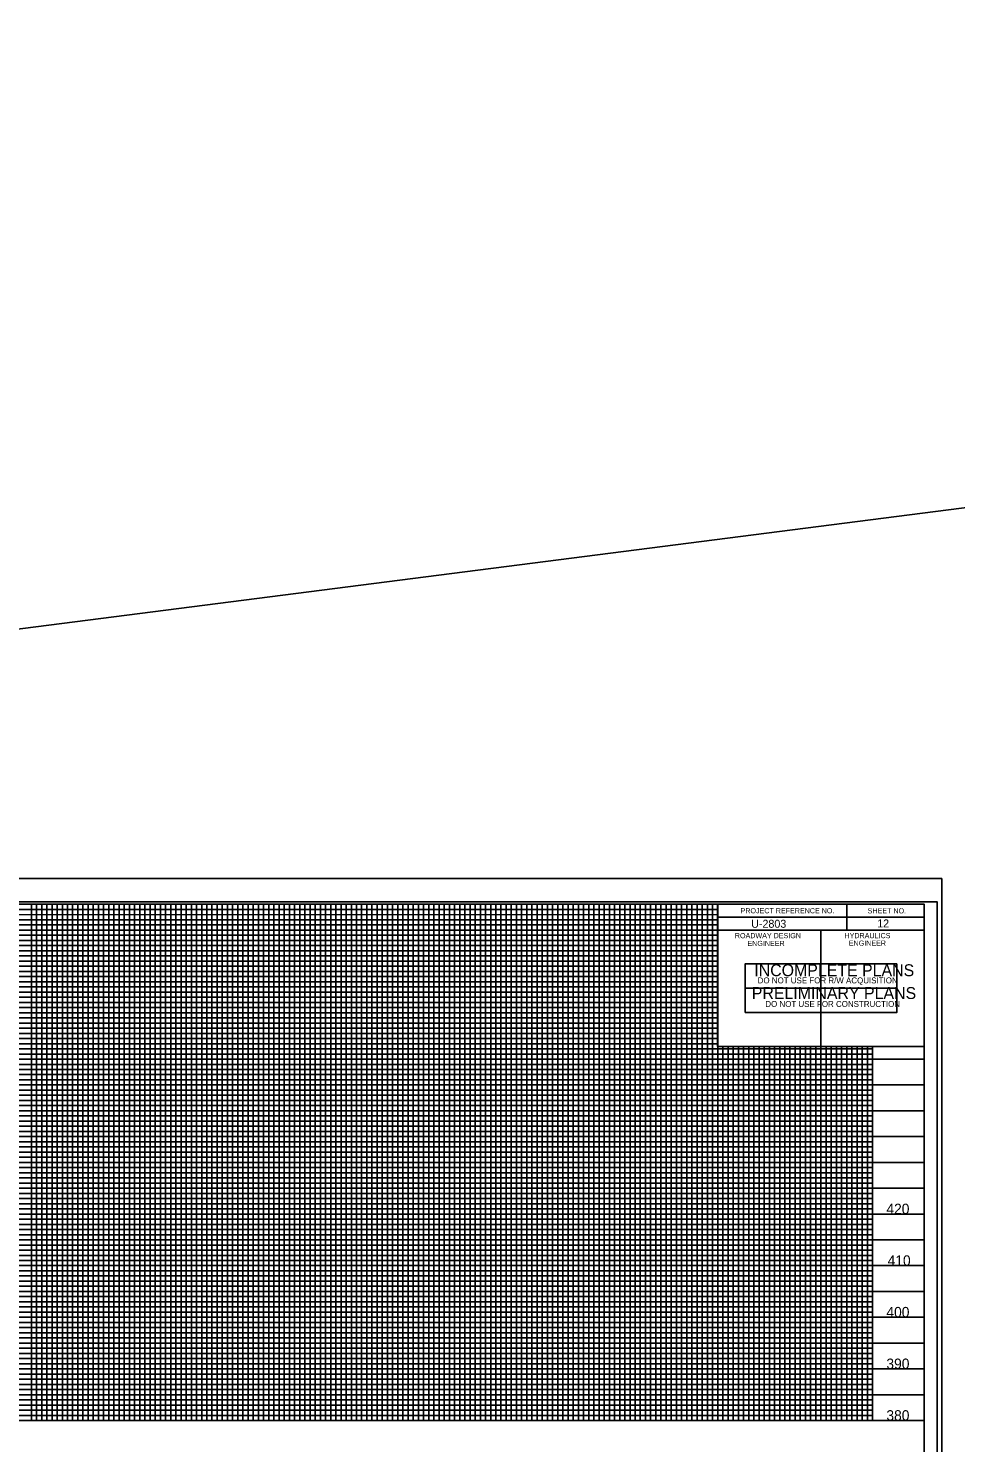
# Model space of a CAD drawing. Extents: x 571503 to 593215, y -77195 to -51828.
# Drawn here: x 588685 to 589583, y -53198 to -51828 of the extents above; entities that cross this region are included whole.
import ezdxf

# ---------------------------------------------------------------- set-up
doc = ezdxf.new("R2010")
doc.units = 0
for name, color, linetype in [('Exist Vertical Profile Vertical Axis Label', 7, 'Continuous'), ('Prop PFL Text', 7, 'Continuous'), ('Sheet Clip Boundary CELL', 7, 'Continuous'), ('Sheet Data Field CELL', 7, 'Continuous'), ('Sheet DOT Grid CELL', 7, 'Continuous'), ('Sheet Plot Border Inside CELL', 7, 'Continuous'), ('Sheet Plot Border Outside CELL', 7, 'Continuous'), ('Sheet Profile CELL', 7, 'Continuous'), ('Sheet Profile Grid Major CELL', 7, 'Continuous'), ('Sheet Profile Grid Middle CELL', 7, 'Continuous'), ('Sheet Profile Grid Minor CELL', 7, 'Continuous'), ('Sheet Sticker Incomplete CELL', 7, 'Continuous'), ('Sheet Sticker Preliminary CELL', 7, 'Continuous')]:
    doc.layers.add(name, color=color, linetype=linetype)

msp = doc.modelspace()

# ---------------------------------------------------------------- linework, layer by layer
at = {"layer": 'Prop PFL Text'}
msp.add_line((571799.6, -54572.4), (593215.4, -51828.4), dxfattribs=at)
at = {"layer": 'Sheet Clip Boundary CELL'}
msp.add_lwpolyline([(588102.5, -52676.9), (588102.5, -53176.9), (589502.5, -53176.9), (589502.5, -52814.5), (589352.4, -52814.5), (589352.4, -52676.9)], close=True, dxfattribs=at)
at = {"layer": 'Sheet DOT Grid CELL'}
for p, q in [((588702.5, -53176.9), (588702.5, -52676.9)), ((588702.5, -53176.9), (588702.5, -52676.9)), ((588752.5, -53176.9), (588752.5, -52676.9)), ((588752.5, -53176.9), (588752.5, -52676.9)), ((588802.5, -53176.9), (588802.5, -52676.9)), ((588802.5, -53176.9), (588802.5, -52676.9)), ((588852.5, -53176.9), (588852.5, -52676.9)), ((588852.5, -53176.9), (588852.5, -52676.9)), ((588902.5, -53176.9), (588902.5, -52676.9)), ((588902.5, -53176.9), (588902.5, -52676.9)), ((588952.5, -53176.9), (588952.5, -52676.9)), ((588952.5, -53176.9), (588952.5, -52676.9)), ((589002.5, -53176.9), (589002.5, -52676.9)), ((589002.5, -53176.9), (589002.5, -52676.9)), ((589052.5, -53176.9), (589052.5, -52676.9)), ((589052.5, -53176.9), (589052.5, -52676.9)), ((589102.5, -53176.9), (589102.5, -52676.9)), ((589102.5, -53176.9), (589102.5, -52676.9)), ((589152.5, -53176.9), (589152.5, -52676.9)), ((589152.5, -53176.9), (589152.5, -52676.9)), ((589202.5, -53176.9), (589202.5, -52676.9)), ((589202.5, -53176.9), (589202.5, -52676.9)), ((589252.5, -53176.9), (589252.5, -52676.9)), ((589252.5, -53176.9), (589252.5, -52676.9)), ((589302.5, -53176.9), (589302.5, -52676.9)), ((589302.5, -53176.9), (589302.5, -52676.9)), ((588052.5, -52726.9), (589352.4, -52726.9)), ((589352.4, -52726.9), (588052.5, -52726.9)), ((588052.5, -52776.9), (589352.4, -52776.9)), ((589352.4, -52776.9), (588052.5, -52776.9)), ((588052.5, -52826.9), (589552.5, -52826.9)), ((589552.5, -52826.9), (588052.5, -52826.9)), ((589352.5, -53176.9), (589352.5, -52814.5)), ((589352.5, -53176.9), (589352.5, -52814.5)), ((589402.5, -53176.9), (589402.5, -52814.5)), ((589402.5, -53176.9), (589402.5, -52814.5)), ((589452.5, -53176.9), (589452.5, -52814.5)), ((589452.5, -53176.9), (589452.5, -52814.5)), ((589502.5, -53176.9), (589502.5, -52814.5)), ((589502.5, -53176.9), (589502.5, -52814.5)), ((589552.5, -53176.9), (589552.5, -52814.5)), ((588052.5, -52876.9), (589552.5, -52876.9)), ((589552.5, -52876.9), (588052.5, -52876.9)), ((588052.5, -52926.9), (589552.5, -52926.9)), ((589552.5, -52926.9), (588052.5, -52926.9)), ((588052.5, -52976.9), (589552.5, -52976.9)), ((589552.5, -52976.9), (588052.5, -52976.9)), ((588052.5, -53026.9), (589552.5, -53026.9)), ((589552.5, -53026.9), (588052.5, -53026.9)), ((588052.5, -53076.9), (589552.5, -53076.9)), ((589552.5, -53076.9), (588052.5, -53076.9)), ((588052.5, -53126.9), (589552.5, -53126.9)), ((589552.5, -53126.9), (588052.5, -53126.9))]:
    msp.add_line(p, q, dxfattribs=at)
at = {"layer": 'Sheet Plot Border Inside CELL'}
msp.add_lwpolyline([(587898.5, -53729.5), (589565, -53729.5), (589565, -52674.4), (587898.5, -52674.4)], close=True, dxfattribs=at)
at = {"layer": 'Sheet Plot Border Outside CELL'}
msp.add_lwpolyline([(587885.5, -53751.9), (589569.5, -53751.9), (589569.5, -52651.9), (587885.5, -52651.9)], close=True, dxfattribs=at)
at = {"layer": 'Sheet Profile CELL'}
for p, q in [((589569.5, -52651.9), (587885.5, -52651.9)), ((589477.5, -52677), (589477.5, -52702)), ((589352.4, -52689.5), (589552.5, -52689.5)), ((589452.5, -52702), (589452.5, -52814.4)), ((588052.5, -53176.9), (589552.5, -53176.9))]:
    msp.add_line(p, q, dxfattribs=at)
for points in [[(589552.5, -52676.9), (588052.5, -52676.9), (588052.5, -53726.9), (589552.5, -53726.9)], [(589352.4, -52676.9), (589552.5, -52676.9), (589552.5, -52702), (589352.4, -52702)], [(589352.4, -52702), (589452.5, -52702), (589452.5, -52814.5), (589352.4, -52814.5)], [(589452.5, -52702), (589552.5, -52702), (589552.5, -52814.5), (589452.5, -52814.5)]]:
    msp.add_lwpolyline(points, close=True, dxfattribs=at)
at = {"layer": 'Sheet Profile Grid Major CELL'}
for points in [[(588652.5, -52676.9), (588702.5, -52676.9), (588702.5, -53176.9), (588752.5, -53176.9), (588752.5, -52676.9), (588802.5, -52676.9), (588802.5, -53176.9), (588852.5, -53176.9), (588852.5, -52676.9), (588902.5, -52676.9), (588902.5, -53176.9), (588952.5, -53176.9), (588952.5, -52676.9), (589002.5, -52676.9), (589002.5, -53176.9), (589052.5, -53176.9), (589052.5, -52676.9), (589102.5, -52676.9), (589102.5, -53176.9), (589152.5, -53176.9), (589152.5, -52676.9), (589202.5, -52676.9), (589202.5, -53176.9), (589252.5, -53176.9), (589252.5, -52676.9), (589302.5, -52676.9), (589302.5, -53176.9), (589352.5, -53176.9), (589352.5, -52676.9), (589378.8, -52676.9)], [(588052.5, -52726.9), (589352.5, -52726.9)], [(589352.5, -52776.9), (588052.5, -52776.9), (588052.5, -52826.9), (589552.5, -52826.9)], [(589402.5, -52814.5), (589402.5, -53176.9), (589452.5, -53176.9), (589452.5, -53176.9), (589452.5, -52814.5)], [(589502.5, -52814.5), (589502.5, -53176.9), (589552.5, -53176.9), (589552.5, -52826.9)], [(589552.5, -52876.9), (588052.5, -52876.9), (588052.5, -52926.9), (589552.5, -52926.9)], [(589552.5, -52976.9), (588052.5, -52976.9), (588052.5, -53026.9), (589552.5, -53026.9)], [(589552.5, -53076.9), (588052.5, -53076.9), (588052.5, -53076.9), (588052.5, -53126.9), (589552.5, -53126.9)]]:
    msp.add_lwpolyline(points, dxfattribs=at)
at = {"layer": 'Sheet Profile Grid Middle CELL'}
msp.add_line((588052.5, -52701.9), (589352.4, -52701.9), dxfattribs=at)
for points in [[(588677.5, -52676.9), (588727.5, -52676.9), (588727.5, -53176.9), (588777.5, -53176.9), (588777.5, -52676.9), (588827.5, -52676.9), (588827.5, -53176.9), (588877.5, -53176.9), (588877.5, -52676.9), (588927.5, -52676.9), (588927.5, -53176.9), (588977.5, -53176.9), (588977.5, -52676.9), (589027.5, -52676.9), (589027.5, -53176.9), (589077.5, -53176.9), (589077.5, -52676.9), (589127.5, -52676.9), (589127.5, -53176.9), (589177.5, -53176.9), (589177.5, -52676.9), (589227.5, -52676.9), (589227.5, -53176.9), (589277.5, -53176.9), (589277.5, -52676.9), (589327.5, -52676.9), (589327.5, -53176.9), (589377.5, -53176.9), (589377.5, -52814.5)], [(589352.5, -52751.9), (588052.5, -52751.9), (588052.5, -52801.9), (589352.5, -52801.9)], [(589377.5, -52914.1), (589377.5, -53176.9), (589427.5, -53176.9), (589427.5, -52814.5)], [(589427.5, -52914.1), (589427.5, -53176.9), (589477.5, -53176.9), (589477.5, -52814.5)], [(589552.5, -52851.9), (588052.5, -52851.9), (588052.5, -52901.9), (589377.5, -52901.9)], [(589377.5, -52901.9), (589552.5, -52901.9)], [(589552.5, -52951.9), (588052.5, -52951.9), (588052.5, -53001.9), (589552.5, -53001.9)], [(589552.5, -53051.9), (588052.5, -53051.9), (588052.5, -53101.9), (589552.5, -53101.9)], [(589552.5, -53151.9), (588052.5, -53151.9)]]:
    msp.add_lwpolyline(points, dxfattribs=at)
at = {"layer": 'Sheet Profile Grid Minor CELL'}
for p, q in [((588102.5, -52681.9), (589352.5, -52681.9)), ((589352.5, -52686.9), (588102.5, -52687.3)), ((588102.5, -52691.9), (589352.5, -52691.9)), ((589352.4, -52811.9), (588102.5, -52811.9)), ((589502.5, -52816.9), (588102.5, -52816.9)), ((589502.5, -52821.9), (588102.5, -52821.9)), ((588102.5, -52831.9), (589502.5, -52831.9)), ((589502.5, -52836.9), (588102.5, -52836.9)), ((588102.5, -52841.9), (589502.5, -52841.9)), ((589502.5, -52861.9), (588102.5, -52861.9)), ((588102.5, -52866.9), (589502.5, -52866.9)), ((589502.5, -52886.9), (588102.5, -52886.9)), ((588102.5, -52891.9), (589502.5, -52891.9)), ((589502.5, -52911.9), (588102.5, -52911.9)), ((588102.5, -52916.9), (589502.5, -52916.9)), ((589502.5, -52921.9), (588102.5, -52921.9)), ((588102.5, -52931.9), (589502.5, -52931.9)), ((589502.5, -52936.9), (588102.5, -52936.9)), ((588102.5, -52941.9), (589502.5, -52941.9)), ((589502.5, -52946.9), (588102.5, -52946.9)), ((588102.5, -52956.9), (589502.5, -52956.9)), ((589502.5, -52961.9), (588102.5, -52961.9)), ((588102.5, -52966.9), (589502.5, -52966.9)), ((589502.5, -52971.9), (588102.5, -52971.9)), ((588102.5, -52981.9), (589502.5, -52981.9)), ((589502.5, -52986.9), (588102.5, -52986.9)), ((588102.5, -52991.9), (589502.5, -52991.9)), ((589502.5, -52996.9), (588102.5, -52996.9)), ((588102.5, -53006.9), (589502.5, -53006.9)), ((589502.5, -53011.9), (588102.5, -53011.9)), ((588102.5, -53016.9), (589502.5, -53016.9)), ((589502.5, -53021.9), (588102.5, -53021.9)), ((588102.5, -53031.9), (589502.5, -53031.9)), ((589502.5, -53036.9), (588102.5, -53036.9)), ((588102.5, -53041.9), (589502.5, -53041.9)), ((589502.5, -53046.9), (588102.5, -53046.9)), ((588102.5, -53056.9), (589502.5, -53056.9)), ((589502.5, -53061.9), (588102.5, -53061.9)), ((589502.5, -53066.9), (588102.5, -53066.9)), ((589502.5, -53071.9), (588102.5, -53071.9)), ((588102.5, -53081.9), (589502.5, -53081.9)), ((589502.5, -53086.9), (588102.5, -53086.9)), ((588102.5, -53091.9), (589502.5, -53091.9)), ((589502.5, -53096.9), (588102.5, -53096.9)), ((588102.5, -53106.9), (589502.5, -53106.9)), ((589502.5, -53111.9), (588102.5, -53111.9)), ((588102.5, -53116.9), (589502.5, -53116.9)), ((589502.5, -53121.9), (588102.5, -53121.9)), ((588102.5, -53131.9), (589502.5, -53131.9)), ((589502.5, -53136.9), (588102.5, -53136.9)), ((588102.5, -53141.9), (589502.5, -53141.9)), ((589502.5, -53146.9), (588102.5, -53146.9)), ((588102.5, -53156.9), (589502.5, -53156.9)), ((589502.5, -53161.9), (588102.5, -53161.9)), ((588102.5, -53166.9), (589502.5, -53166.9))]:
    msp.add_line(p, q, dxfattribs=at)
for points in [[(588682.5, -53176.9), (588687.5, -53176.9), (588687.5, -52676.9), (588692.5, -52676.9), (588692.5, -53176.9), (588697.5, -53176.9), (588697.5, -52676.9), (588707.5, -52676.9), (588707.5, -53176.9), (588712.5, -53176.9), (588712.5, -52676.9), (588717.5, -52676.9), (588717.5, -53176.9), (588722.5, -53176.9), (588722.5, -52676.9), (588732.5, -52676.9), (588732.5, -53176.9), (588737.5, -53176.9), (588737.5, -52676.9), (588742.5, -52676.9), (588742.5, -53176.9), (588747.5, -53176.9), (588747.5, -52676.9), (588757.5, -52676.9), (588757.5, -53176.9), (588757.5, -53176.9), (588762.5, -53176.9), (588762.5, -52676.9), (588767.5, -52676.9), (588767.5, -53176.9), (588772.5, -53176.9), (588772.5, -52676.9), (588782.5, -52676.9), (588782.5, -53176.9), (588787.5, -53176.9), (588787.5, -52676.9), (588792.5, -52676.9), (588792.5, -53176.9), (588797.5, -53176.9), (588797.5, -52676.9), (588807.5, -52676.9), (588807.5, -53176.9), (588812.5, -53176.9), (588812.5, -52676.9), (588817.5, -52676.9), (588817.5, -53176.9), (588822.5, -53176.9), (588822.5, -52676.9), (588832.5, -52676.9), (588832.5, -53176.9), (588837.5, -53176.9), (588837.5, -52676.9), (588842.5, -52676.9), (588842.5, -53176.9), (588847.5, -53176.9), (588847.5, -52676.9), (588857.5, -52676.9), (588857.5, -53176.9), (588862.5, -53176.9), (588862.5, -52676.9), (588867.5, -52676.9), (588867.5, -53176.9), (588872.5, -53176.9), (588872.5, -52676.9), (588882.5, -52676.9), (588882.5, -53176.9), (588887.5, -53176.9), (588887.5, -52676.9), (588892.5, -52676.9), (588892.5, -53176.9), (588897.5, -53176.9), (588897.5, -52676.9), (588907.5, -52676.9), (588907.5, -53176.9), (588912.2, -53176.4), (588912.5, -53176.9), (588912.5, -52676.9), (588917.5, -52676.9), (588917.5, -53176.9), (588922.5, -53176.9), (588922.5, -52676.9), (588932.5, -52676.9), (588932.5, -53176.9), (588937.5, -53176.9)], [(588937.5, -53176.9), (588937.5, -52676.9), (588942.5, -52676.9), (588942.5, -53176.9), (588947.5, -53176.9), (588947.5, -52676.9), (588957.5, -52676.9), (588957.5, -53176.9), (588962.5, -53176.9), (588962.5, -52676.9), (588967.5, -52676.9), (588967.5, -53176.9), (588972.5, -53176.9), (588972.5, -52676.9), (588982.5, -52676.9), (588982.5, -53176.9), (588987.5, -53176.9), (588987.5, -52676.9), (588992.5, -52676.9), (588992.5, -53176.9), (588997.5, -53176.9), (588997.5, -52676.9), (589007.5, -52676.9), (589007.5, -53176.9), (589012.5, -53176.9), (589012.5, -52676.9), (589017.5, -52676.9), (589017.5, -53176.9), (589022.5, -53176.9), (589022.5, -52676.9), (589032.5, -52676.9), (589032.5, -53176.9), (589037.5, -53176.9), (589037.5, -52676.9), (589042.5, -52676.9), (589042.5, -53176.9), (589047.5, -53176.9), (589047.5, -52676.9), (589057.5, -52676.9), (589057.5, -53176.9), (589062.5, -53176.9), (589062.5, -52676.9), (589067.5, -52676.9), (589067.5, -53176.9), (589072.5, -53176.9), (589072.5, -52676.9), (589082.5, -52676.9), (589082.5, -53176.9), (589087.5, -53176.9), (589087.5, -52676.9), (589092.5, -52676.9), (589092.5, -53176.9), (589097.5, -53176.9), (589097.5, -52676.9), (589107.5, -52676.9), (589107.5, -53176.9), (589112.5, -53176.9), (589112.5, -52676.9), (589117.5, -52676.9), (589117.5, -53176.9), (589122.5, -53176.9), (589122.5, -52676.9), (589132.5, -52676.9), (589132.5, -53176.9), (589137.5, -53176.9), (589137.5, -52676.9), (589142.5, -52676.9), (589142.5, -53176.9), (589147.5, -53176.9), (589147.5, -52676.9), (589157.5, -52676.9), (589157.5, -53176.9), (589162.5, -53176.9), (589162.5, -52676.9), (589167.5, -52676.9), (589167.5, -53176.9), (589172.5, -53176.9), (589172.5, -52676.9), (589182.5, -52676.9), (589182.5, -53176.9), (589187.5, -53176.9), (589187.5, -52676.9), (589192.5, -52676.9), (589192.5, -53176.9), (589197.5, -53176.9), (589197.5, -52676.9), (589207.5, -52676.9), (589207.5, -53176.9), (589212.5, -53176.9), (589212.5, -52676.9), (589217.5, -52676.9), (589217.5, -53176.9), (589222.5, -53176.9), (589222.5, -52676.9), (589232.5, -52676.9), (589232.5, -53176.9), (589237.5, -53176.9), (589237.5, -52676.9), (589242.5, -52676.9), (589242.5, -53176.9)], [(589242.5, -53176.9), (589247.5, -53176.9), (589247.5, -52676.9), (589257.5, -52676.9), (589257.5, -53176.9), (589262.5, -53176.9), (589262.5, -52676.9), (589267.5, -52676.9), (589267.5, -53176.9), (589272.5, -53176.9), (589272.5, -52676.9), (589282.5, -52676.9), (589282.5, -53176.9), (589287.5, -53176.9), (589287.5, -52676.9), (589292.5, -52676.9), (589292.5, -53176.9), (589297.5, -53176.9), (589297.5, -52676.9), (589307.5, -52676.9), (589307.5, -53176.9), (589312.5, -53176.9), (589312.5, -52676.9), (589317.5, -52676.9), (589317.5, -53176.9), (589322.5, -53176.9), (589322.5, -52676.9), (589332.5, -52676.9), (589332.5, -53176.9), (589337.5, -53176.9), (589337.5, -52676.9), (589342.5, -52676.9), (589342.5, -53176.9), (589347.5, -53176.9), (589347.5, -52676.9), (589357.5, -52676.9)], [(589352.5, -52696.9), (588102.5, -52696.9), (588102.5, -52706.9), (589352.5, -52706.9)], [(589352.4, -52711.9), (588102.5, -52711.9), (588102.5, -52716.9), (589352.5, -52716.9)], [(589352.5, -52721.9), (588102.5, -52721.9), (588102.5, -52731.9), (589352.5, -52731.9)], [(589352.5, -52736.9), (588102.5, -52736.9), (588102.5, -52741.9), (589352.5, -52741.9)], [(589352.5, -52746.9), (588102.5, -52746.9), (588102.5, -52756.9), (589352.5, -52756.9)], [(589352.5, -52761.9), (588102.5, -52761.9), (588102.5, -52766.9), (589352.5, -52766.9)], [(589352.5, -52771.9), (588102.5, -52771.9), (588102.5, -52781.9), (589352.5, -52781.9)], [(589352.5, -52796.9), (588102.5, -52796.9), (588102.5, -52806.9), (589352.5, -52806.9)], [(589352.5, -52787), (588102.6, -52787), (588102.6, -52791.9), (589352.5, -52791.9)], [(589357.5, -52814.5), (589357.5, -53176.9), (589362.5, -53176.9), (589362.5, -52814.5)], [(589367.5, -52814.5), (589367.5, -53176.9), (589372.5, -53176.9), (589372.5, -52814.5)], [(589382.5, -52814.5), (589382.5, -53176.9), (589382.5, -53176.9), (589387.5, -53176.9), (589392.5, -53176.9), (589392.5, -52814.5)], [(589387.5, -52814.5), (589387.5, -53176.9)], [(589397.5, -52814.5), (589397.4, -53176.9), (589402.4, -53176.9), (589407.5, -53176.9), (589407.5, -52814.5)], [(589407.5, -52914.1), (589407.5, -53176.9), (589412.5, -53176.9), (589412.5, -52814.5)], [(589417.5, -52814.5), (589417.5, -53176.9), (589422.5, -53176.9), (589422.5, -52814.5)], [(589432.5, -52814.5), (589432.5, -53176.9), (589437.5, -53176.9), (589437.5, -52814.5)], [(589442.5, -52814.5), (589442.5, -53176.9), (589447.5, -53176.9), (589447.5, -52814.5)], [(589457.5, -52814.5), (589457.5, -53176.9), (589462.5, -53176.9), (589462.5, -52814.5)], [(589467.5, -52814.5), (589467.5, -53176.9), (589472.5, -53176.9), (589472.5, -52814.5)], [(589482.5, -52814.5), (589482.5, -53176.9), (589487.5, -53176.9), (589487.5, -52814.5)], [(589492.5, -52814.5), (589492.5, -53176.9), (589497.5, -53176.9), (589497.5, -52814.5)], [(589502.5, -52846.9), (588102.5, -52846.9), (588102.5, -52856.9), (589502.5, -52856.9)], [(589502.5, -52871.9), (588102.5, -52871.9), (588102.5, -52881.9), (589502.5, -52881.9)], [(589502.5, -52896.9), (588102.5, -52896.9), (588102.5, -52906.9), (589502.5, -52906.9)], [(589502.5, -53171.9), (588102.5, -53171.9)]]:
    msp.add_lwpolyline(points, dxfattribs=at)
at = {"layer": 'Sheet Sticker Incomplete CELL'}
msp.add_lwpolyline([(589379, -52758.2), (589379, -52734.7), (589526, -52734.7), (589526, -52758.2)], close=True, dxfattribs=at)
at = {"layer": 'Sheet Sticker Preliminary CELL'}
msp.add_lwpolyline([(589379, -52781.7), (589379, -52758.2), (589526, -52758.2), (589526, -52781.7)], close=True, dxfattribs=at)

# ---------------------------------------------------------------- texts
at = {"layer": 'Exist Vertical Profile Vertical Axis Label'}
for s, p in [('420', (589515.9, -52976.9)), ('410', (589517.1, -53026.9)), ('400', (589515.9, -53076.9)), ('390', (589515.9, -53126.9)), ('380', (589515.9, -53176.9))]:
    msp.add_text(s, height=10, dxfattribs=at).set_placement(p)
at = {"layer": 'Sheet Data Field CELL'}
for s, p in [('U-2803   ', (589384.9, -52699.6)), ('12 ', (589507, -52699.3))]:
    msp.add_text(s, height=7.75, dxfattribs=at).set_placement(p)
at = {"layer": 'Sheet Profile CELL'}
for s, p in [('PROJECT REFERENCE NO.', (589374.6, -52685.6)), ('SHEET NO.', (589497.8, -52685.7)), ('ROADWAY DESIGN', (589369.1, -52709.7)), ('HYDRAULICS', (589475.3, -52709.7)), ('ENGINEER', (589381.3, -52717.3)), ('ENGINEER', (589479.5, -52717))]:
    msp.add_text(s, height=5, dxfattribs=at).set_placement(p)
at = {"layer": 'Sheet Sticker Incomplete CELL'}
for s, height, p in [('INCOMPLETE PLANS', 11.52, (589387.9, -52746.5)), ('DO NOT USE FOR R/W ACQUISITION', 5.76, (589391.2, -52753.5))]:
    msp.add_text(s, height=height, dxfattribs=at).set_placement(p)
at = {"layer": 'Sheet Sticker Preliminary CELL'}
for s, height, p in [('PRELIMINARY PLANS', 11.52, (589385.5, -52768.6)), ('DO NOT USE FOR CONSTRUCTION', 5.76, (589398.6, -52776.3))]:
    msp.add_text(s, height=height, dxfattribs=at).set_placement(p)

doc.saveas('drawing.dxf')
